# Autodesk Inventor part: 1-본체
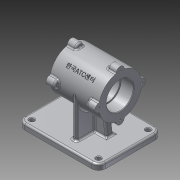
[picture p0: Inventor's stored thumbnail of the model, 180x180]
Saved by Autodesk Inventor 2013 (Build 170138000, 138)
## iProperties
Created: 2015-12
Part Number: 1-본체
Material: 알루미늄 6061
Document SubType Name: Modeling
Designer: default
Mass: 1041.34 g
Surface Area: 815.354 cm^2
Volume: 432.573 cm^3
Density: 2.40731 g/cm^3
Author: default
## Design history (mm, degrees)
sketch "스케치1"
  geometry: L1 (-80, 55)-(60, 55); L2 (60, 55)-(60, -55); L3 (60, -55)-(-80, -55); L4 (-80, -55)-(-80, 55); 2 further points
  constraints: 8 end point, 2 parallel, 1 horizontal, 1 horizontal alignment, 1 midpoint, 1 perpendicular
  dimensions: "d0" = 140 distance between parallel lines of L2 L4; "d2" = 110 distance between parallel lines of L3 L1; "d110" = 80 distance from line of L4 point (0, 0)
extrude "돌출1" new body sketch "스케치1" distance "d3" = 10; taper "d4" = 0 deg
sketch "스케치2"
  geometry: L1 (42.5, 80)-(-42.5, 80); L2 (-42.5, 80)-(-42.5, 117); L3 (-42.5, 117)-(42.5, 117); L4 (42.5, 117)-(42.5, 80); L5 (-60, 0)-(80, 0) reference; L6 (80, 0)-(80, 10) reference; 1 further point
  constraints: 8 end point, 2 parallel, 1 horizontal, 1 perpendicular
  dimensions: "d5" = 74 diameter of L3 L1; "d7" = 85 distance between parallel lines of L2 L4; "d8" = 80 distance from line of L1.start L5; "d9" = 37.5 distance between parallel lines of L6 L4
revolve "회전1" sketch "스케치2" stored, may be unused: angle "d10" = 90 deg
sketch "스케치3"
  geometry: L1 (-80, 55)-(-80, -55) reference; L2 (-4, 37)-(4, 37); L3 (4, 37)-(4, -37); L4 (4, -37)-(-4, -37); L5 (-4, -37)-(-4, 37); 2 further points
  constraints: 8 end point, 2 parallel, 1 horizontal, 1 horizontal alignment, 1 midpoint, 1 perpendicular
  dimensions: "d11" = 74 distance between parallel lines of L4 L2; "d13" = 8 distance between parallel lines of L3 L5; "d14" = 76 distance between parallel lines of L1 L5
extrude "돌출2" join sketch "스케치3" stored distance "d15" = 0; taper "d16" = 0 deg
sketch "스케치5"
  geometry: L1 (42.5, 43)-(42.5, 117) reference; L2 (-42.5, 43)-(-42.5, 117) reference; L3 (42.5, 80)-(-42.5, 80); L4 (42.5, 103.5)-(20.5, 103.5); L5 (20.5, 103.5)-(20.5, 101); L6 (20.5, 101)-(-20.5, 101); L7 (-20.5, 101)-(-20.5, 103.5); L8 (-20.5, 103.5)-(-42.5, 103.5); 1 further point
  constraints: 12 end point, 3 parallel, 2 midpoint, 2 perpendicular, 2 point on line
  dimensions: "d24" = 42 diameter of L6 L3; "d26" = 47 diameter of L4 L3; "d27" = 47 diameter of L8 L3; "d28" = 22 distance from line of L2 L7.end; "d29" = 22 distance from line of L1 L4.end
revolve "회전2" sketch "스케치5" stored, may be unused: angle "d30" = 90 deg
sketch "스케치6"
  geometry: C1 r 23.5 at (0, 0) reference; C2 r 7 at (0, 37); 2 further points
  constraints: 2 vertical alignment, 1 centre point, 1 other
  dimensions: "d31" = 14 diameter of C2
extrude "돌출4" join sketch "스케치6" distance "d33" = 15; taper "d34" = 0 deg
sketch "스케치7"
  geometry: C1 r 23.5 at (0, 0) reference; C2 r 7 at (0, 37); 2 further points
  constraints: 2 vertical alignment, 1 centre point, 1 other
  dimensions: "d38" = 14 diameter of C2
extrude "돌출5" join sketch "스케치7" distance "d40" = 15; taper "d41" = 0 deg
sketch "스케치8"
  geometry: A1 r 7 centre (-37, -37) between (-36.338, -30.031) and (-36.338, -43.969) reference; 2 further points
  constraints: 1 coincident
hole "구멍1" sketch "스케치8" at (-37, -37) diameter "d45" = 3.242; stored, may be unused: countersink angle "d49" = 90 deg, drill point angle "d51" = 118 deg; dims "d46" = 9, "d47" = 4, "d48" = 2, "d50" = 11
sketch "스케치9"
  geometry: A1 r 7 centre (0, 0) between (6.969, -0.662) and (-6.969, -0.662) reference; 2 further points
  constraints: 1 coincident
hole "구멍2" sketch "스케치9" at (0, 0) diameter "d55" = 3.242; stored, may be unused: countersink angle "d59" = 90 deg, drill point angle "d61" = 118 deg; dims "d56" = 9, "d57" = 4, "d58" = 2, "d60" = 11
sketch "스케치10"
  geometry: L1 (60, 55)-(-80, 55) reference; L2 (-80, 55)-(-80, -55) reference; C1 r 4 at (-68, 43); 1 further point
  constraints: 1 centre point
  dimensions: "d65" = 8 diameter of C1; "d67" = 12 distance from line of L2 C1.centre; "d68" = 12 distance from line of L1 C1.centre
extrude "돌출6" cut sketch "스케치10" distance "d69" = 15; taper "d70" = 0 deg
chamfer "모따기1" distance "d77" = 1; stored, may be unused: second distance "d78" = 2, angle "d79" = 45 deg
fillet "모깎기1" dims "d80" = 3
fillet "모깎기2" dims "d81" = 12
fillet "모깎기3" dims "d82" = 3
fillet "모깎기4" dims "d83" = 3
node "작업축1"
node "작업 평면1"
node "작업 평면2"
sketch "스케치12"
  geometry: L1 (-42.5, 18.921)-(-42.5, -18.921) reference; L2 (42.5, 18.921)-(42.5, -18.921) reference; 3 further points
  constraints: 1 horizontal alignment, 1 midpoint, 1 other
  dimensions: "d86" = 42.5 distance from line of L1 point (0, 0)
feature "엠보싱1" sketch "스케치12" dims "d0" = 140, "d2" = 110, "d87" = 0.5, "d88" = 0, "d110" = 80
fillet "모깎기5" dims "d89" = 0.3
sketch "스케치13"
  geometry: L1 (-24.5, 43)-(24.5, 43) reference; L2 (-48, 10)-(68, 10) reference; L3 (4, 58.929)-(4, 13) reference; L4 (20.948, 43)-(25, 10); A1 r 3 centre (7, 13) between (4, 13) and (7, 10) reference; A2 r 3 centre (7, 40) between (7, 43) and (4, 40) reference; 1 further point
  constraints: 2 end point, 2 point on line
  dimensions: "d90" = 97 deg angle of L4 L2; "d112" = 25 horizontal distance of L4.end point (0, 0)
feature "리브1" sketch "스케치13" dims "d92" = 1, "d93" = 12, "d94" = 0, "d95" = 0, "d96" = 1, "d97" = 1
sketch "스케치14"
  geometry: L1 (-24.5, 43)-(24.5, 43) reference; L2 (-4, 13)-(-4, 58.929) reference; L3 (-48, 10)-(68, 10) reference; L4 (-20.948, 43)-(-25, 10); L5 (-1, 80)-(-1, 13) reference; 4 further points
  constraints: 2 end point, 2 point on line, 1 other
  dimensions: "d98" = 97 deg angle of L4 L3; "d111" = 25 horizontal distance of L4.end point (0, 0)
feature "리브2" sketch "스케치14" dims "d100" = 1, "d101" = 12, "d102" = 0, "d103" = 0, "d104" = 1, "d105" = 1
fillet "모깎기7" dims "d107" = 3
node "솔리드1"
pattern_circular "원형 패턴1" dims angle "d36" = 360 deg
pattern_circular "원형 패턴2" dims angle "d43" = 360 deg
pattern_circular "원형 패턴3" dims angle "d53" = 360 deg
pattern_circular "원형 패턴4" dims angle "d63" = 360 deg
pattern_linear "직사각형 패턴1" dims "d73" = 86, "d76" = 116
other parameters: "d84" = 45 deg, "d85" = -37.5
